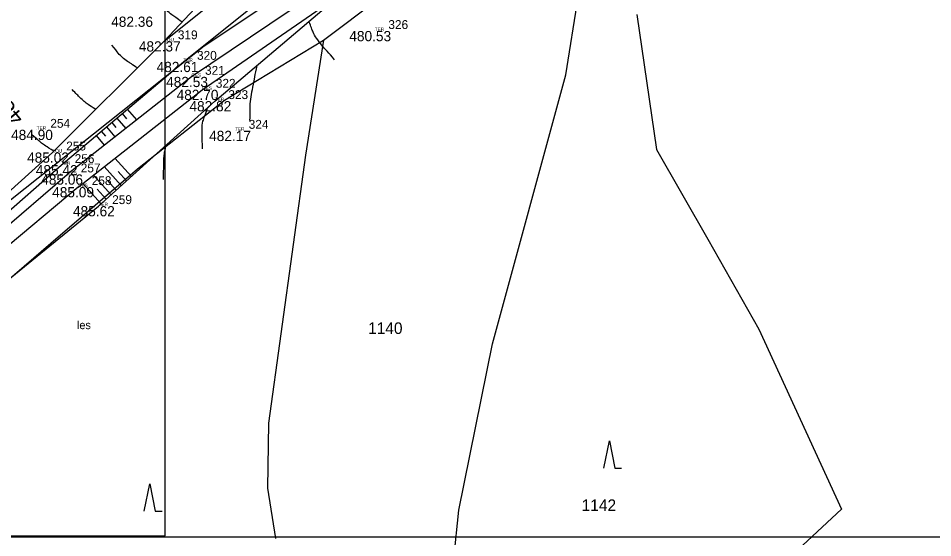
# Model space of a CAD drawing. Extents: x -604848 to -603227, y -1111879 to -1109838.
# Drawn here: x -603773.6 to -603639.4, y -1110678.1 to -1110601.8 of the extents above; entities that cross this region are included whole.
import ezdxf

# ---------------------------------------------------------------- set-up
doc = ezdxf.new("R2010")
doc.units = 0
for name, color, linetype in [('1', 7, 'Continuous'), ('10', 7, 'Continuous'), ('14', 7, 'Continuous'), ('18', 7, 'Continuous'), ('19', 7, 'Continuous'), ('20', 7, 'Continuous'), ('23', 7, 'Continuous'), ('4', 7, 'Continuous'), ('7', 7, 'Continuous'), ('8', 7, 'Continuous'), ('9', 7, 'Continuous'), ('Default', 7, 'Continuous')]:
    doc.layers.add(name, color=color, linetype=linetype)

# ---------------------------------------------------------------- blocks, each defined once
blk = doc.blocks.new('Z3080')
at = {"layer": '23'}
for p, q in [((-0.8, 0), (0, 4)), ((0, 4), (0.8, 0)), ((0.8, 0), (1.8, 0))]:
    blk.add_line(p, q, dxfattribs=at)
blk = doc.blocks.new('POINT_DISPLAY')
at = {"layer": 'Default'}
blk.add_line((0, 0), (0, 0), dxfattribs=at)

msp = doc.modelspace()

# ---------------------------------------------------------------- linework, layer by layer
at = {"layer": '1'}
for p, q in [((-603746.35, -1110605.91), (-603732.25, -1110596.47)), ((-603728.86, -1110605.05), (-603716.75, -1110595.9)), ((-603693.28, -1110610.14), (-603691.26, -1110597.62)), ((-603682.85, -1110601.29), (-603679.99, -1110621.11)), ((-603792.75, -1110642.77), (-603746.35, -1110605.91)), ((-603743.36, -1110613.87), (-603728.86, -1110605.05)), ((-603728.86, -1110605.05), (-603731.5, -1110621.94)), ((-603704.02, -1110649.64), (-603693.28, -1110610.14)), ((-603756.15, -1110623.92), (-603743.36, -1110613.87)), ((-603731.5, -1110621.94), (-603736.93, -1110661.27)), ((-603679.99, -1110621.11), (-603672.46, -1110634.28)), ((-603768.87, -1110634.85), (-603756.15, -1110623.92)), ((-603781.58, -1110645.78), (-603768.87, -1110634.85)), ((-603672.46, -1110634.28), (-603664.94, -1110647.44)), ((-603664.94, -1110647.44), (-603658.88, -1110660.67)), ((-603708.98, -1110674.01), (-603704.02, -1110649.64)), ((-603658.88, -1110660.67), (-603652.81, -1110673.9)), ((-603736.93, -1110661.27), (-603737.07, -1110670.78)), ((-603737.07, -1110670.78), (-603735.87, -1110678.2)), ((-603712.75, -1110710.43), (-603708.98, -1110674.01)), ((-603652.81, -1110673.9), (-603674.76, -1110694.1))]:
    msp.add_line(p, q, dxfattribs=at)
for points in [[(-603752.05, -1110677.81), (-603752.05, -1109837.81), (-604346.05, -1109837.81), (-604346.05, -1110677.81), (-603752.05, -1110677.81)], [(-603227.31, -1110677.93), (-603227.31, -1109837.93), (-603821.31, -1109837.93), (-603821.31, -1110677.93), (-603227.31, -1110677.93)]]:
    msp.add_lwpolyline(points, dxfattribs=at)
at = {"layer": '10'}
for p, q in [((-603752.21, -1110605.22), (-603735.9, -1110587.69)), ((-603768.59, -1110621.54), (-603752.21, -1110605.22)), ((-603788.75, -1110639.65), (-603768.59, -1110621.54))]:
    msp.add_line(p, q, dxfattribs=at)
at = {"layer": '4'}
for p, q in [((-603727.52, -1110596.49), (-603748.22, -1110610.44)), ((-603746.64, -1110612.34), (-603726.06, -1110598.13)), ((-603748.22, -1110610.44), (-603766.46, -1110624.76)), ((-603764.85, -1110626.62), (-603746.64, -1110612.34)), ((-603786.43, -1110641.95), (-603766.46, -1110624.76)), ((-603764.85, -1110626.62), (-603785.26, -1110643.65))]:
    msp.add_line(p, q, dxfattribs=at)
at = {"layer": '7'}
for p, q in [((-603752.21, -1110605.22), (-603733.49, -1110590.18)), ((-603749.4, -1110608.24), (-603731.13, -1110593.58)), ((-603744.8, -1110614), (-603726.06, -1110598.13)), ((-603767.35, -1110623.39), (-603749.4, -1110608.24)), ((-603761.85, -1110629.41), (-603744.8, -1110614)), ((-603787.39, -1110641.05), (-603767.35, -1110623.39)), ((-603783.41, -1110646.93), (-603761.85, -1110629.41))]:
    msp.add_line(p, q, dxfattribs=at)
for points in [[(-603749.59, -1110602.4), (-603750.35, -1110601.82), (-603751.18, -1110601.34), (-603751.85, -1110600.67), (-603752.49, -1110600.04), (-603753.03, -1110599.33), (-603753.62, -1110598.66)], [(-603727.22, -1110607.93), (-603728.11, -1110606.86), (-603729.1, -1110605.87), (-603729.9, -1110604.71), (-603730.4, -1110603.98), (-603730.63, -1110603.11), (-603730.99, -1110602.31)], [(-603756.15, -1110609.14), (-603756.88, -1110608.62), (-603757.66, -1110608.17), (-603758.34, -1110607.57), (-603758.95, -1110607.04), (-603759.39, -1110606.37), (-603759.91, -1110605.77)], [(-603738.63, -1110608.78), (-603738.91, -1110610.2), (-603739.18, -1110611.62), (-603739.46, -1110613.06), (-603739.7, -1110614.31), (-603739.61, -1110615.59), (-603739.69, -1110616.85)], [(-603762.24, -1110615.21), (-603762.81, -1110614.83), (-603763.41, -1110614.51), (-603763.94, -1110614.06), (-603764.57, -1110613.53), (-603765.12, -1110612.9), (-603765.71, -1110612.32)], [(-603745.93, -1110615.02), (-603746.18, -1110616.03), (-603746.7, -1110617.01), (-603746.7, -1110618.05), (-603746.7, -1110619.04), (-603746.66, -1110620.03), (-603746.63, -1110621.02)], [(-603768.4, -1110621.34), (-603769, -1110620.94), (-603769.65, -1110620.59), (-603770.22, -1110620.14), (-603770.72, -1110619.74), (-603771.19, -1110619.31), (-603771.67, -1110618.89)], [(-603751.98, -1110620.49), (-603752.09, -1110621.14), (-603752.29, -1110621.79), (-603752.3, -1110622.45), (-603752.33, -1110623.46), (-603752.35, -1110624.48), (-603752.37, -1110625.49)]]:
    msp.add_open_spline(points, degree=3, dxfattribs=at)
at = {"layer": '8'}
for p, q in [((-603757.63, -1110615.19), (-603756.29, -1110616.77)), ((-603759.16, -1110616.48), (-603757.86, -1110618.01)), ((-603758.39, -1110615.83), (-603757.74, -1110616.61)), ((-603760.69, -1110617.77), (-603759.44, -1110619.25)), ((-603759.92, -1110617.12), (-603759.29, -1110617.88)), ((-603762.21, -1110619.06), (-603761.01, -1110620.48)), ((-603761.45, -1110618.41), (-603760.84, -1110619.14)), ((-603757.02, -1110625.04), (-603759.44, -1110622.37)), ((-603758.51, -1110626.39), (-603761.01, -1110623.61)), ((-603757.76, -1110625.71), (-603758.99, -1110624.35)), ((-603761.47, -1110629.07), (-603764.17, -1110626.08)), ((-603759.99, -1110627.73), (-603762.59, -1110624.85)), ((-603759.25, -1110627.06), (-603760.53, -1110625.64)), ((-603760.73, -1110628.4), (-603762.06, -1110626.93))]:
    msp.add_line(p, q, dxfattribs=at)

# ---------------------------------------------------------------- block references
at = {"layer": '18'}
for p in [(-603721.32, -1110603.71), (-603752.21, -1110605.22), (-603749.4, -1110608.24), (-603748.22, -1110610.44), (-603746.64, -1110612.34), (-603744.8, -1110614), (-603770.92, -1110618.21), (-603741.81, -1110618.36), (-603768.59, -1110621.54), (-603767.35, -1110623.39), (-603766.46, -1110624.76), (-603764.85, -1110626.62), (-603761.85, -1110629.41)]:
    msp.add_blockref('POINT_DISPLAY', p, dxfattribs=at)
at = {"layer": '23'}
for p in [(-603686.89, -1110667.86), (-603754.33, -1110674.17)]:
    msp.add_blockref('Z3080', p, dxfattribs=at)

# ---------------------------------------------------------------- texts
at = {"layer": '14'}
for s, p in [('1140', (-603722.3, -1110648.17)), ('1142', (-603690.96, -1110674.15))]:
    msp.add_text(s, height=1.7, dxfattribs=at).set_placement(p)
at = {"layer": '18'}
for s, p in [('TER', (-603721.32, -1110603.71)), ('LOU', (-603752.21, -1110605.22)), ('TER', (-603749.4, -1110608.24)), ('CES', (-603748.22, -1110610.44)), ('CES', (-603746.64, -1110612.34)), ('TER', (-603744.8, -1110614)), ('TER', (-603770.92, -1110618.21)), ('TER', (-603741.81, -1110618.36)), ('LOU', (-603768.59, -1110621.54)), ('TER', (-603767.35, -1110623.39)), ('CES', (-603766.46, -1110624.76)), ('CES', (-603764.85, -1110626.62)), ('TER', (-603761.85, -1110629.41))]:
    msp.add_text(s, height=0.5, dxfattribs=at).set_placement(p)
at = {"layer": '19'}
for s, p in [('326', (-603719.32, -1110603.42)), ('319', (-603750.21, -1110604.92)), ('320', (-603747.4, -1110607.94)), ('321', (-603746.22, -1110610.14)), ('322', (-603744.64, -1110612.04)), ('323', (-603742.8, -1110613.7)), ('254', (-603768.92, -1110617.91)), ('324', (-603739.81, -1110618.06)), ('255', (-603766.59, -1110621.24)), ('256', (-603765.35, -1110623.09)), ('257', (-603764.46, -1110624.46)), ('258', (-603762.85, -1110626.32)), ('259', (-603759.85, -1110629.11))]:
    msp.add_text(s, height=1.3, dxfattribs=at).set_placement(p)
at = {"layer": '20'}
for s, p in [('482.36 ', (-603759.99, -1110603.1)), ('480.53 ', (-603725.05, -1110605.21)), ('482.37 ', (-603755.93, -1110606.72)), ('482.61 ', (-603753.33, -1110609.74)), ('482.53 ', (-603751.93, -1110611.94)), ('482.70 ', (-603750.39, -1110613.84)), ('482.82 ', (-603748.51, -1110615.5)), ('484.90 ', (-603774.68, -1110619.71)), ('482.17 ', (-603745.62, -1110619.86)), ('485.02 ', (-603772.33, -1110623.04)), ('485.42 ', (-603771.05, -1110624.89)), ('485.06 ', (-603770.26, -1110626.26)), ('485.09 ', (-603768.65, -1110628.12)), ('485.62 ', (-603765.6, -1110630.91))]:
    msp.add_text(s, height=1.5, dxfattribs=at).set_placement(p)
at = {"layer": '7'}
msp.add_text('485', height=2.5, rotation=129.6, dxfattribs=at).set_placement((-603772.65, -1110616.38))
at = {"layer": '9'}
msp.add_text('les', height=1.2, dxfattribs=at).set_placement((-603765.02, -1110647.46))

doc.saveas('drawing.dxf')
